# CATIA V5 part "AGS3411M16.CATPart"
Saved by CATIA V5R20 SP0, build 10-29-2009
Part number: AGS3411M16
Definition: NONE
Nomenclature: AGS3411M16
Source: Unknown
Description: AGS3411M16
Bounding box of the stored display mesh (mm): x -35 to 33, y -17.347 to 17.347, z -14 to 14
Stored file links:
  C:\Users\Utente\Desktop\IO LAVORO\3D X SITO CF\X SITO\PLASTICA\AGS\AGS3411M16.CATPart
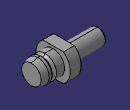
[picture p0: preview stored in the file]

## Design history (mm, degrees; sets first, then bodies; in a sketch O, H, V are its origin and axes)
Body1 "AGS3411M16" (main body)
  Solid1: solid without history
